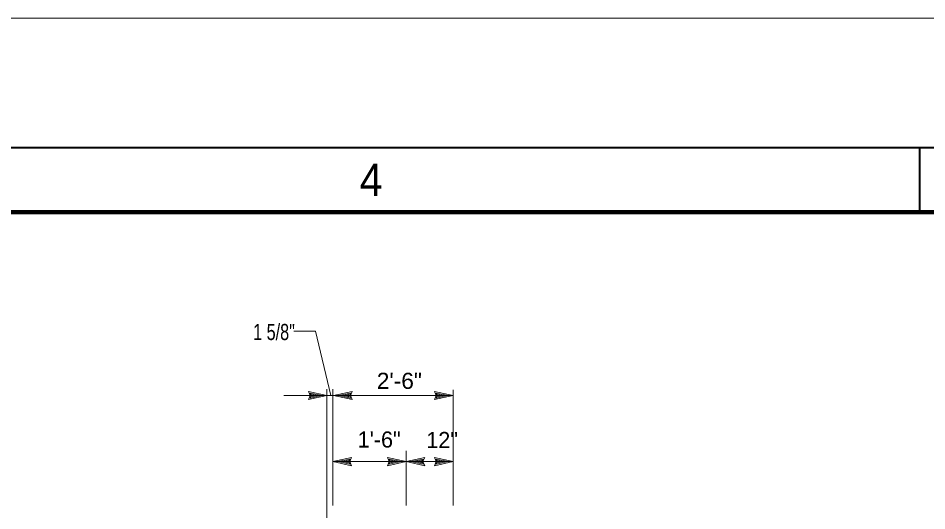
# Model space of a CAD drawing. Extents: x -28.1 to 13.9, y -16.1 to 13.9.
# Drawn here: x -18.12 to -11.09, y 10.06 to 13.87 of the extents above; entities that cross this region are included whole.
import ezdxf
from ezdxf.enums import TextEntityAlignment as Align

# ---------------------------------------------------------------- set-up
doc = ezdxf.new("R2010")
doc.units = 0
doc.header["$LTSCALE"] = 0.05
doc.layers.add('1', color=7, linetype='Continuous', lineweight=13)

msp = doc.modelspace()

# ---------------------------------------------------------------- linework, layer by layer
at = {"layer": '1', "lineweight": 40}
msp.add_line((-11.14304, 12.87269), (-11.14304, 12.37269), dxfattribs=at)
at = {"layer": '1'}
for p, q in [((-15.72804, 10.95169), (-15.87204, 10.98269)), ((-15.76504, 10.95169), (-15.85904, 10.97169)), ((-15.85004, 10.95169), (-15.85904, 10.97169)), ((-15.72804, 7.45469), (-15.72804, 11.00169)), ((-15.68204, 10.10269), (-15.68204, 11.00169)), ((-15.67704, 10.95169), (-15.53304, 10.98269)), ((-15.64004, 10.95169), (-15.54604, 10.97169)), ((-15.54604, 10.97169), (-15.55504, 10.95169)), ((-14.75304, 10.95169), (-14.89704, 10.98269)), ((-14.79004, 10.95169), (-14.88404, 10.97169)), ((-14.87504, 10.95169), (-14.88404, 10.97169)), ((-14.75304, 10.10269), (-14.75304, 10.99669)), ((-15.72804, 10.95169), (-15.87204, 10.92069)), ((-15.76504, 10.95169), (-15.85904, 10.93169)), ((-15.85904, 10.93169), (-15.85004, 10.95169)), ((-15.80104, 10.95169), (-15.84604, 10.96069)), ((-15.84204, 10.95169), (-15.84604, 10.96069)), ((-15.80104, 10.95169), (-15.84604, 10.94169)), ((-15.84604, 10.94169), (-15.84204, 10.95169)), ((-15.67704, 10.95169), (-15.53304, 10.92069)), ((-15.64004, 10.95169), (-15.54604, 10.93169)), ((-15.60404, 10.95169), (-15.55904, 10.96169)), ((-15.60404, 10.95169), (-15.55904, 10.94269)), ((-15.55904, 10.96169), (-15.56304, 10.95169)), ((-15.56304, 10.95169), (-15.55904, 10.94269)), ((-15.55504, 10.95169), (-15.54604, 10.93169)), ((-14.75304, 10.95169), (-14.89704, 10.92069)), ((-14.79004, 10.95169), (-14.88404, 10.93169)), ((-14.88404, 10.93169), (-14.87504, 10.95169)), ((-14.82604, 10.95169), (-14.87104, 10.96069)), ((-14.86704, 10.95169), (-14.87104, 10.96069)), ((-14.82604, 10.95169), (-14.87104, 10.94169)), ((-14.87104, 10.94169), (-14.86704, 10.95169)), ((-15.11604, 10.10269), (-15.11604, 10.52469)), ((-15.68204, 10.44069), (-15.53804, 10.47169)), ((-15.68204, 10.44069), (-15.53804, 10.40969)), ((-15.64504, 10.44069), (-15.55104, 10.46069)), ((-15.64504, 10.44069), (-15.55104, 10.42069)), ((-15.60904, 10.44069), (-15.56404, 10.45069)), ((-15.60904, 10.44069), (-15.56404, 10.43169)), ((-15.56404, 10.45069), (-15.56804, 10.44069)), ((-15.56804, 10.44069), (-15.56404, 10.43169)), ((-15.55104, 10.46069), (-15.56004, 10.44069)), ((-15.56004, 10.44069), (-15.55104, 10.42069)), ((-15.11604, 10.44069), (-15.26004, 10.47169)), ((-15.11604, 10.44069), (-15.26004, 10.40969)), ((-15.15304, 10.44069), (-15.24704, 10.46069)), ((-15.23804, 10.44069), (-15.24704, 10.46069)), ((-15.15304, 10.44069), (-15.24704, 10.42069)), ((-15.24704, 10.42069), (-15.23804, 10.44069)), ((-15.18904, 10.44069), (-15.23404, 10.44969)), ((-15.23004, 10.44069), (-15.23404, 10.44969)), ((-15.18904, 10.44069), (-15.23404, 10.43069)), ((-15.23404, 10.43069), (-15.23004, 10.44069)), ((-15.11604, 10.44069), (-14.97204, 10.47169)), ((-15.11604, 10.44069), (-14.97204, 10.40969)), ((-15.07904, 10.44069), (-14.98504, 10.46069)), ((-15.07904, 10.44069), (-14.98504, 10.42069)), ((-15.04304, 10.44069), (-14.99804, 10.45069)), ((-15.04304, 10.44069), (-14.99804, 10.43169)), ((-14.99804, 10.45069), (-15.00204, 10.44069)), ((-15.00204, 10.44069), (-14.99804, 10.43169)), ((-14.98504, 10.46069), (-14.99404, 10.44069)), ((-14.99404, 10.44069), (-14.98504, 10.42069)), ((-14.75304, 10.44069), (-14.89704, 10.47169)), ((-14.75304, 10.44069), (-14.89704, 10.40969)), ((-14.79004, 10.44069), (-14.88404, 10.46069)), ((-14.87504, 10.44069), (-14.88404, 10.46069)), ((-14.79004, 10.44069), (-14.88404, 10.42069)), ((-14.88404, 10.42069), (-14.87504, 10.44069)), ((-14.82604, 10.44069), (-14.87104, 10.44969)), ((-14.86704, 10.44069), (-14.87104, 10.44969)), ((-14.82604, 10.44069), (-14.87104, 10.43069)), ((-14.87104, 10.43069), (-14.86704, 10.44069))]:
    msp.add_line(p, q, dxfattribs=at)
for points in [[(-28.14304, 13.87269), (13.85696, 13.87269), (13.85696, -16.12731)], [(-15.69804, 10.95169), (-15.81604, 11.45169), (-15.98404, 11.45169)], [(-15.87204, 10.92069), (-15.85804, 10.95169), (-15.87204, 10.98269)], [(-15.53304, 10.98269), (-15.54704, 10.95169), (-15.53304, 10.92069)], [(-14.89704, 10.92069), (-14.88304, 10.95169), (-14.89704, 10.98269)], [(-16.06304, 10.95169), (-15.72804, 10.95169), (-15.67704, 10.95169), (-14.75304, 10.95169)], [(-15.68204, 10.44069), (-15.11604, 10.44069), (-14.75304, 10.44069)], [(-15.53804, 10.47169), (-15.55204, 10.44069), (-15.53804, 10.40969)], [(-15.26004, 10.40969), (-15.24604, 10.44069), (-15.26004, 10.47169)], [(-14.97204, 10.47169), (-14.98604, 10.44069), (-14.97204, 10.40969)], [(-14.89704, 10.40969), (-14.88304, 10.44069), (-14.89704, 10.47169)]]:
    msp.add_lwpolyline(points, dxfattribs=at)
at = {"layer": '1', "lineweight": 40}
msp.add_lwpolyline([(-27.14304, -15.12731), (-27.14304, 12.87269), (12.85696, 12.87269), (12.85696, -15.12731)], close=True, dxfattribs=at)
at = {"layer": '1', "lineweight": 90}
msp.add_lwpolyline([(-25.64304, 12.37269), (12.35696, 12.37269), (12.35696, -14.62731), (-25.64304, -14.62731)], close=True, dxfattribs=at)

# ---------------------------------------------------------------- texts
at = {"layer": '1'}
for s, height, width, p in [('4', 0.25, 0.95, (-15.38654, 12.49769)), ('2\'-6"', 0.125, 1.05, (-15.16816, 11.00369))]:
    msp.add_text(s, height=height, dxfattribs=dict(at, width=width)).set_placement(p, align=Align.CENTER)
at = {"layer": '1', "width": 0.75}
msp.add_text('1 5/8"', height=0.125, dxfattribs=at).set_placement((-15.97631, 11.38169), align=Align.RIGHT)
at = {"layer": '1'}
msp.add_text('1\'-6"', height=0.125, dxfattribs=at).set_placement((-15.32423, 10.54969), align=Align.CENTER)
msp.add_text('12"', height=0.125, dxfattribs=at).set_placement((-14.96004, 10.54569))

doc.saveas('drawing.dxf')
